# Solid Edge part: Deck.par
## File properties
Author: morva
Template: iso metric part.par
Last saved by: morva
Revision: 73
Application: Solid Edge
Density: 2712.000 kg/m^3
Accuracy: 0.990
Username: morva
Material: Aluminum, 6061-T6
Face Style: Aluminum
Fill Style: ANSI38(Aluminum)
Virtual Style: Polished aluminum
Grouping: Metals\Aluminium Alloys
LibraryName: Materials
Coef. of Thermal Exp: 2.3e-05
Thermal Conductivity: 180.0
Specific Heat: 920.0
Modulus of Elasticity: 68947570000.0
Poisson's Ratio: 0.33
Yield Stress: 275790280.0
Ultimate Stress: 310264065.0
Elongation: 0.0
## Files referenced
..\..\DeckAssemlby.asm
C:\Users\morva\OneDrive\Dokumentumok\egyetem\VII. félév\Szakdolgozat\3D modellek\DeckAssemlby.asm
v\Szakdolgozat\3D modellek\DeckAssemlby.asm
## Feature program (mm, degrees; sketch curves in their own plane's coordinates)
sketch for "unnamed RevolvedProtrusion 1" plane through (0, 0, 0) normal (0, 0, 1) x-axis (1, 0, 0)
  line (-21, 10) -> (21, 10)
  line (21, 10) -> (21, 17.5)
  line (21, 17.5) -> (32.5, 17.5)
  line (32.5, 17.5) -> (32.5, 27.5)
  line (32.5, 27.5) -> (-32.5, 27.5)
  line (-32.5, 27.5) -> (-32.5, 17.5)
  line (-32.5, 17.5) -> (-21, 17.5)
  line (-21, 17.5) -> (-21, 10)
  dimension (linear) = 32.5
  dimension (linear) = 21
  dimension (linear) = 32.5
revolve "unnamed RevolvedProtrusion 1" add full turn 360 deg
sketch for "unnamed Protrusion 1" plane through (0, 0, 0) normal (0, -1, 0) x-axis (1, 0, 0)
  line (32.5, -17.5) -> (-32.5, -17.5)
  line (-32.5, -17.5) -> (-32.5, -27.5)
  line (-32.5, -27.5) -> (187.6352, -306.9331)
  line (205, -208.4523) -> (187.6352, -306.9331)
  line (32.5, -27.5) -> (205, -208.4523)
  line (32.5, -17.5) -> (32.5, -27.5)
  dimension (linear) = 205
  dimension (linear) = 205
  dimension (linear) = 32.5
extrude "unnamed Protrusion 1" add finite 50 symmetric
sketch for "ExtrudedProtrusion_2" plane through (191.225, 0, -286.5742) normal (0.984808, 0, -0.173648) x-axis (0.173648, 0, 0.984808)
  line (79.327, 125) -> (-920.673, 125)
  line (-920.673, 125) -> (-920.673, -125)
  line (-920.673, -125) -> (79.327, -125)
  line (79.327, -125) -> (79.327, 125)
  dimension (linear) = 920.673
  dimension (linear) = 920.673
extrude "ExtrudedProtrusion_2" add finite 50 along +normal
chamfer "Chamfer_2" setback 5
sketch for "ExtrudedCutout_1" plane through (113.0965, 0, -729.6629) normal (-0.984808, 0, 0.173648) x-axis (-0.173648, 0, -0.984808)
  line (470.749, 56) -> (390.749, 56)
  line (390.749, 56) -> (307.7866, 37.5)
  line (307.7866, 37.5) -> (307.7866, -37.5)
  line (390.749, -56) -> (307.7866, -37.5)
  line (390.749, -56) -> (470.749, -56)
  line (470.749, 56) -> (470.749, -56)
  dimension (linear) = 470.749
  dimension (linear) = 470.749
  dimension (linear) = 307.7866
  dimension (linear) = 390.749
  dimension (linear) = 390.749
  dimension (linear) = 390.749
extrude "ExtrudedCutout_1" cut finite 630.0605 symmetric
sketch for "unnamed Cutout 1" plane through (113.0965, 0, -729.6629) normal (-0.984808, 0, 0.173648) x-axis (0, -1, 0)
  line (-70, -470.749) -> (-70, -410.749)
  line (-70, -410.749) -> (-125, -274.749)
  line (-125, -274.749) -> (-125, -470.749)
  line (-125, -470.749) -> (-70, -470.749)
  dimension (linear) = 70
  dimension (linear) = 125
extrude "unnamed Cutout 1" cut through along -normal
mirror "unnamed Mirror 1" of "unnamed Cutout 1"
pattern "unnamed Pattern 1"
sketch for "unnamed Cutout 2" plane through (77.9179, 70, -1200.7104) normal (0, 1, 0) x-axis (-0.173648, 0, -0.984808)
  line (-29.251, 27.1524) -> (0.749, 27.1524)
  line (0.749, 17.1524) -> (0.749, 27.1524)
  line (-29.251, 17.1524) -> (0.749, 17.1524)
  dimension (linear) = 29.251
extrude "unnamed Cutout 2" cut through along -normal
fillet "Round_5" radius 10
fillet "Round_6" radius 10
chamfer "Chamfer_3" setback 3
sketch for "ExtrudedCutout_4" plane through (169.1528, 0, -699.6905) normal (0.984808, 0, -0.173648) x-axis (-0.173648, 0, -0.984808)
extrude "ExtrudedCutout_4" cut finite 45 along -normal
mirror "unnamed Mirror 2" of "ExtrudedCutout_4"
pattern "unnamed Pattern 2"
sketch for "ExtrudedCutout_5" plane through (169.1528, 0, -699.6905) normal (0.984808, 0, -0.173648) x-axis (-0.173648, 0, -0.984808)
  line (312.5945, -63) -> (395.6873, -48.3485)
  line (420.7298, -53.9328) -> (395.6873, -48.3485)
  line (312.5945, -73) -> (420.7298, -53.9328)
  line (312.5945, -73) -> (312.5945, -63)
  dimension (linear) = 312.5945
extrude "ExtrudedCutout_5" cut finite 25 along -normal
chamfer "Chamfer_5" setback 6
sketch for "Hole_1" plane through (178.4782, 0, -646.8037) normal (0.984808, 0, -0.173648) x-axis (0.173648, 0, 0.984808)
hole "Hole_1" diameter 8 finite  VBottomAngle = 118 deg; ThreadDepth = 20 mm
sketch for "unnamed Hole 1" plane through (178.4782, 0, -646.8037) normal (0.984808, 0, -0.173648) x-axis (0.173648, 0, 0.984808)
hole "unnamed Hole 1" finite
sketch for "unnamed Hole 2" plane through (178.4782, 0, -646.8037) normal (0.984808, 0, -0.173648) x-axis (0.173648, 0, 0.984808)
  hole centre (406.2973, 0) bore radius 3.3235
hole "unnamed Hole 2" finite
sketch for "unnamed Hole 3" plane through (178.4782, 0, -646.8037) normal (0.984808, 0, -0.173648) x-axis (0.173648, 0, 0.984808)
  hole centre (306.2973, -115) bore radius 3.3235
hole "unnamed Hole 3" finite
sketch for "unnamed Hole 4" plane through (178.4782, 0, -646.8037) normal (0.984808, 0, -0.173648) x-axis (0.173648, 0, 0.984808)
hole "unnamed Hole 4" finite
pattern "unnamed Pattern 3" of "Hole_1", "unnamed Hole 1", "unnamed Hole 2", "unnamed Hole 3", "unnamed Hole 4"
mirror "unnamed Mirror 3" of "unnamed Pattern 3" about plane through (0, 0, 0) normal (0, -1, 0)
hole "unnamed Hole 5" finite
hole "unnamed Hole 6" finite
hole "unnamed Hole 7" finite
hole "unnamed Hole 8" finite
hole "unnamed Hole 9" finite
sketch for "ExtrudedCutout_9" plane through (157.0717, 125, -632.8749) normal (0, 1, 0) x-axis (0.173648, 0, 0.984808)
  circle centre (66.2973, 3.5) radius 7.5
extrude "ExtrudedCutout_9" cut finite 18 along -normal
sketch for "unnamed Cutout 3" plane through (137.5102, 107, -747.517) normal (0, 1, 0) x-axis (0, 0, 1)
  circle centre (179.3244, 34.5207) radius 4
extrude "unnamed Cutout 3" cut through along -normal
sketch for "ExtrudedCutout_12" plane through (-196.4398, 0, -239.2103) normal (0.173648, 0, 0.984808) x-axis (0, 1, 0)
  line (-9, -188.6986) -> (-9, -390)
  line (9, -390) -> (-9, -390)
  line (9, -390) -> (9, -188.6986)
  line (9, -188.6986) -> (-9, -188.6986)
  dimension (linear) = 9
extrude "ExtrudedCutout_12" cut finite 275.5902 along +normal
sketch for "ExtrudedCutout_13" plane through (0, 0, -112.2486) normal (0, 0, 1) x-axis (1, 0, 0)
  line (21.4145, 13) -> (-32.5, 13)
  line (-32.5, -13) -> (-32.5, 13)
  line (34.2642, -13) -> (-32.5, -13)
  line (34.2642, 13) -> (34.2642, -13)
  line (21.4145, 13) -> (34.2642, 13)
extrude "ExtrudedCutout_13" cut finite 85 along +normal
sketch for "ExtrudedCutout_14" plane through (149.4446, 0, -609.9042) normal (0.984808, 0, -0.173648) x-axis (-0.173648, 0, -0.984808)
  line (-405, 9) -> (-305, 9)
  line (-305, 9) -> (-305, -9)
  line (-305, -9) -> (-405, -9)
  line (-405, -9) -> (-405, 9)
extrude "ExtrudedCutout_14" cut finite 15 along -normal
fillet "Round_7" radius 2
fillet "Round_8" radius 2
sketch for "Hole_11" plane through (119.9124, 0, -691.0081) normal (-0.984808, 0, 0.173648) x-axis (-0.173648, 0, -0.984808)
  hole centre (322.0377, 0) bore radius 3.3235
hole "Hole_11" nominal diameter 8 finite  VBottomAngle = 118 deg; ThreadDepth = 9 mm
sketch for "unnamed Hole 10" plane through (119.9124, 0, -691.0081) normal (-0.984808, 0, 0.173648) x-axis (-0.173648, 0, -0.984808)
  hole centre (281.0377, 0) bore radius 3.3235
hole "unnamed Hole 10" finite
pattern "unnamed Pattern 4" of "Hole_11", "unnamed Hole 10"
fillet "Round_10" radius 6
fillet "Round_11" radius 5
extrude "ExtrudedCutout_18" cut finite 6
extrude "ExtrudedCutout_19" cut finite 35
fillet "unnamed Round 1"
chamfer "Chamfer_6" setback 20
fillet "Round_13" radius 5
sketch for "unnamed Cutout 4" plane through (169.1528, 0, -699.6905) normal (0.984808, 0, -0.173648) x-axis (-0.173648, 0, -0.984808)
extrude "unnamed Cutout 4" cut finite 45 along -normal
sketch for "ExtrudedProtrusion_4" plane through (140.2395, 0, -604.5212) normal (0.984808, 0, -0.173648) x-axis (0.173648, 0, 0.984808)
extrude "ExtrudedProtrusion_4" add finite 45 along +normal
mirror "unnamed Mirror 4" of "ExtrudedProtrusion_4" about plane through (0, 0, 0) normal (0, -1, 0)
extrude "unnamed Protrusion 2" add finite 45
sketch for "unnamed Cutout 5" plane through (167.4163, 0, -709.5386) normal (0.984808, 0, -0.173648) x-axis (0.173648, 0, 0.984808)
  line (500, 25) -> (405.9588, 25)
  line (500, 25) -> (500, 125)
  line (430, 125) -> (500, 125)
  line (286.7834, 125) -> (430, 125)
  line (400, 30) -> (286.7834, 125)
  line (400, 30) -> (405.9588, 25)
extrude "unnamed Cutout 5" cut finite 153.3471 along -normal
mirror "unnamed Mirror 5" of "unnamed Cutout 5"
pattern "unnamed Pattern 5"
sketch for "unnamed Cutout 6" plane through (110.8702, 25, -162.852) normal (0, 1, 0) x-axis (-0.173648, 0, -0.984808)
  line (28.5621, -100.6182) -> (65.3848, -150.6182)
  line (28.5621, -150.6182) -> (65.3848, -150.6182)
  line (28.5621, -100.6182) -> (28.5621, -150.6182)
extrude "unnamed Cutout 6" cut finite 111.9339 along -normal
sketch for "unnamed Protrusion 3" plane through (86.25, -13, -167.0908) normal (0, 1, 0) x-axis (-0.173648, 0, -0.984808)
  line (-128.1365, 77.1731) -> (-126.5261, 78.3591)
  line (-126.5261, 78.3591) -> (22.5963, -124.1283)
  line (22.5963, -124.1283) -> (58.9959, -172.4944)
  line (60.2256, -174.1283) -> (58.9959, -172.4944)
  line (56.9351, -174.1283) -> (60.2256, -174.1283)
  line (20.1124, -124.1283) -> (56.9351, -174.1283)
  line (20.1124, -124.1283) -> (-128.1365, 77.1731)
  dimension (linear) = 128.1365
extrude "unnamed Protrusion 3" add through along +normal
fearecompute load "unnamed FEARecomputeLoad 1"
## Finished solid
Body 1: solid body, 97 faces, 242 edges, 140 vertices.
  Faces by surface: plane 63, cylinder 27, cone 7
  Edges by curve: line 191, circle 51
Bounding box of the edges (mm): 280.346 x 250.000 x 1229.443, from (-32.5, -125, -1201.9425) to (247.8462, 125, 27.5).
Cylindrical faces by radius (mm): R3.3235 x11, R4 x1, R5 x2, R7.5 x1, R10 x9, R17.5 x2, R27.5 x1
Conical faces (half-angle, radius in mm at the cone's reference point): 45 deg R7 x1, 45 deg R13 x1, 59 deg R3.3235 x5
Planar faces by outward normal: +x 2, +y 9, -x 4, -y 8, -z 1, oblique 39
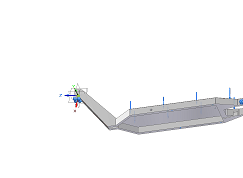
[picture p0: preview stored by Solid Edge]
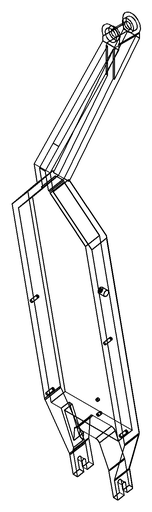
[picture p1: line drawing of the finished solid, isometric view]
